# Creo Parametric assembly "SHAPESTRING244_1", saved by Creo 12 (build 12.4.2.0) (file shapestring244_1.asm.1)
Units: Custom; MM, KILOGRAM, SECS

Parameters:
  PTC_WM_ITERATION = "0"
  PTC_WM_VERSION = "-.0"
  PTC_WM_LIFECYCLE_STATE = "In Work"
  PTC_WM_LIFECYCLE = "MO_CADDocument"
  PTC_WM_CREATED_BY = "Maximilian Roepper (Z0017RMS: MO)"
  PTC_WM_CREATED_ON = "18-Sep-26 11:36:42 AM"
  PTC_WM_MODIFIED_BY = "Maximilian Roepper (Z0017RMS: MO)"
  PTC_WM_MODIFIED_ON = "18-Sep-26 11:36:46 AM"
  PDMLINKNUMBER = "PDM000071454967"
  PTC_WM_NAME = "shapestring244_1.asm"
  PTC_WM_NUMBER = "PDM000071454967"

Other parameters: WEIGHT, WEIGHT_FACTOR, WEIGHT_ADD, MC_ERRORS, SUPPLIER, ISPOSITIONINGASSEMBLY

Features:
  1. coordinate system
  2. imported feature
  3. component "SHAPESTRING097_1"
  4. component "SHAPESTRING243_1"

Other named items: DRW_VIEW_ORG, ROUGH-GROB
